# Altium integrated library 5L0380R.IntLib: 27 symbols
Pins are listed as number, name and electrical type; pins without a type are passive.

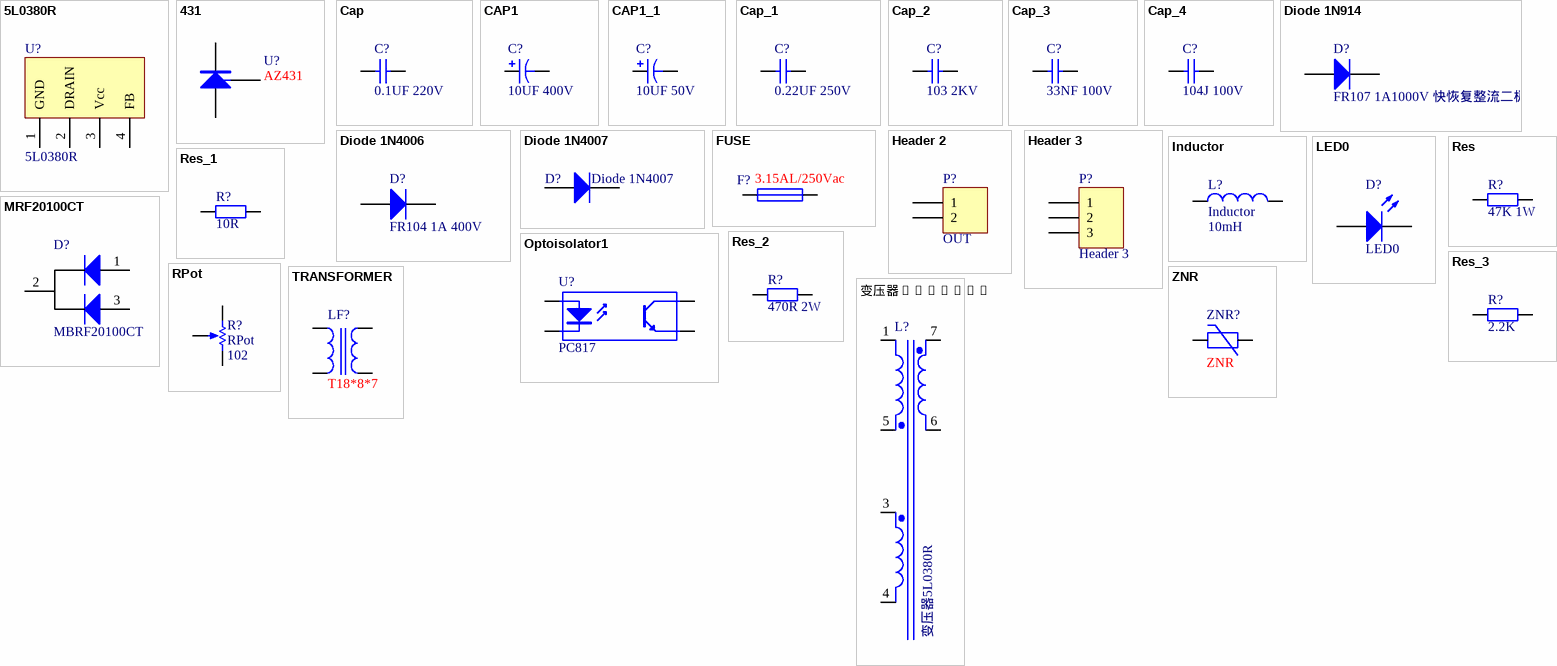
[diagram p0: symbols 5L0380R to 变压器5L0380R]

## 5L0380R
designator U?
footprint 5L0380R
pins: 1 GND, 2 DRAIN, 3 Vcc, 4 FB

## 431
designator U?, comment AZ431
footprint TL431
pins: 1 C, 2 R, 3 A
2 alternate drawings of the same symbol

## Cap
designator C?, comment 0.1UF 220V
Capacitor; Value: LC-1206_C
simulation model CAP (Capacitor)
signal-integrity model Cap
footprint X电容
pins: 1, 2

## CAP1
designator C?, comment 10UF 400V
Electronic Capacitor
footprint 10UF 400v
pins: 1, 2

## CAP1_1
designator C?, comment 10UF 50V
Electronic Capacitor
footprint 25V 100UF
pins: 1, 2

## Cap_1
designator C?, comment 0.22UF 250V
Capacitor; Value: LC-1206_C
simulation model CAP (Capacitor)
signal-integrity model Cap
footprint Y电容 2.2NF
pins: 1, 2

## Cap_2
designator C?, comment 103 2KV
Capacitor; Value: LC-1206_C
simulation model CAP (Capacitor)
signal-integrity model Cap
footprint 2KV电容
pins: 1, 2

## Cap_3
designator C?, comment 33NF 100V
Capacitor; Value: LC-1206_C
simulation model CAP (Capacitor)
signal-integrity model Cap
footprint 33NF 100V电容
pins: 1, 2

## Cap_4
designator C?, comment 104J 100V
Capacitor; Value: LC-1206_C
simulation model CAP (Capacitor)
signal-integrity model Cap
footprint 100J 100V
pins: 1, 2

## Diode 1N914
designator D?, comment FR107 1A1000V 快恢复整流二极管
High Conductance Fast Diode
footprint DO-35 (Diode, Axial; Body 3.8 x 1.9 mm (LxDia. max), Lead Dia. 0.53 mm (max))
simulation model 1N914 (DIODE)
signal-integrity model 1N914
pins: 1 A, 2 K

## Diode 1N4006
designator D?, comment FR104 1A 400V
1 Amp General Purpose Rectifier
simulation model 1N4006 (DIODE)
signal-integrity model 1N4006
footprint DO-35 (Diode, Axial; Body 3.8 x 1.9 mm (LxDia. max), Lead Dia. 0.53 mm (max))
pins: 1 A, 2 K

## Diode 1N4007
designator D?
1 Amp General Purpose Rectifier
simulation model 1N4007 (DIODE)
signal-integrity model 1N4007
footprint 整流二极管
pins: 1 A, 2 K

## FUSE
designator F?, comment 3.15AL/250Vac
footprint 熔断丝
pins: 1, 2
2 alternate drawings of the same symbol

## Header 2
designator P?, comment OUT
Header, 2-Pin
signal-integrity model Connector
pins: 1, 2

## Header 3
designator P?
Header, 3-Pin
signal-integrity model Connector
footprint HDR3X1_D1 (5.08mm端子)
pins: 1, 2, 3

## Inductor
designator L?  value 10mH
Code_IEC: 1005
simulation model INDUCTOR (Inductor)
signal-integrity model Inductor
footprint 滤波电感
pins: 1, 2

## LED0
designator D?
Typical INFRARED GaAs LED
simulation model LED0 (Diode)
footprint 插件LED
pins: 1 A, 2 K

## MRF20100CT
designator D?, comment MBRF20100CT
footprint MBRF20100CT
pins: 1, 2, 3

## Optoisolator1
designator U?, comment PC817
4-Pin Phototransistor Optocoupler
footprint PC817
pins: 1 A "Anode", 2 K "Cathode", 3 E "Emitter", 4 C "Collector"

## Res
designator R?, comment 47K 1W
resistance
footprint 1W电阻
pins: 1, 2

## Res_1
designator R?, comment 10R
resistance
footprint AXIAL-0.4 (Axial Device, Thru-Hole; 2 Leads; 0.4 in Pin Spacing)
pins: 1, 2

## Res_2
designator R?, comment 470R 2W
resistance
footprint 2W电阻
pins: 1, 2

## Res_3
designator R?, comment 2.2K
resistance
footprint R2512
footprint R1206
footprint R0805
footprint R0603
footprint R1210
footprint R1812
footprint 0805A
footprint LC-0805_R
footprint LC-0603_R
pins: 1, 2

## RPot
designator R?  value 102
Potentiometer; Sim Note: Enter the Resistance value and the set point into parameter fields.; Set Position: 0.5
simulation model POT (Potentiometer)
footprint 100R滑动变阻器
pins: 1, 2, 3
1 alternate drawing of the same symbol

## TRANSFORMER
designator LF?, comment T18*8*7
footprint 共模电感
pins: 1, 2, 3, 4
2 alternate drawings of the same symbol

## ZNR
designator ZNR?
footprint 压敏电阻
pins: 1, 2
2 alternate drawings of the same symbol

## 变压器5L0380R
designator L?
footprint 变压器
pins: 1, 3, 4, 5, 6, 7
